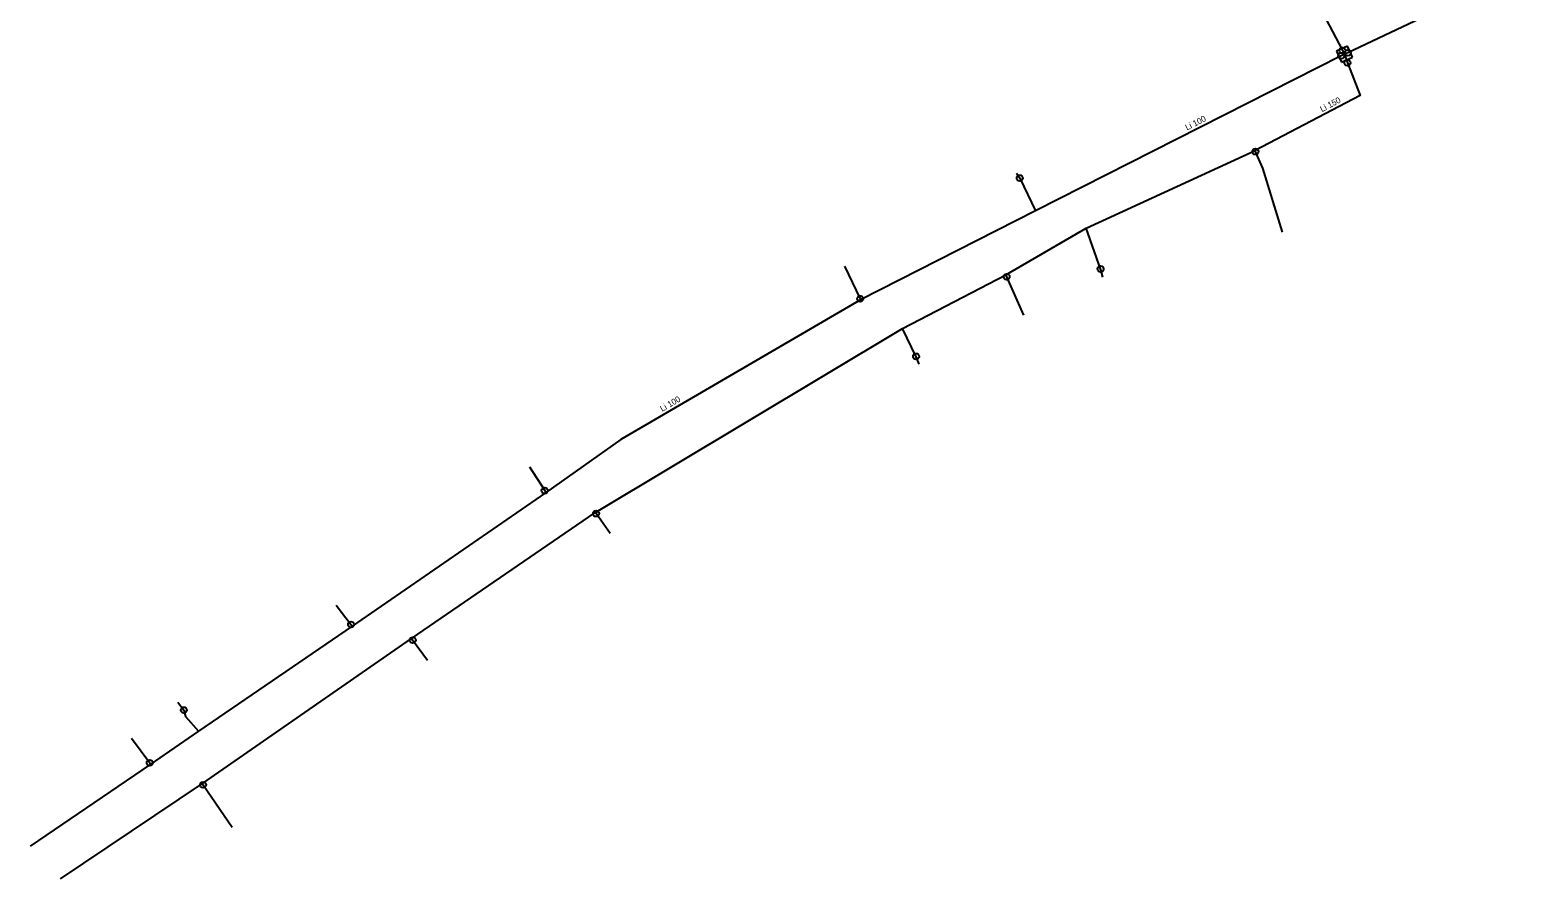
# Model space of a CAD drawing. Extents: x -684724 to -684366, y -1163865 to -1163489.
# Drawn here: x -684620.3 to -684495.3, y -1163846.5 to -1163776.1 of the extents above; entities that cross this region are included whole.
import ezdxf

# ---------------------------------------------------------------- set-up
doc = ezdxf.new("R2010")
doc.units = 0
for name, color, linetype in [('Popis vodovodních řadů', 7, 'Continuous'), ('Vod přípojky-voda pitná', 7, 'Continuous'), ('Vodovodní řad', 7, 'Continuous'), ('Vodovodní šachty', 7, 'Continuous'), ('Vodovodní šoupata', 7, 'Continuous')]:
    doc.layers.add(name, color=color, linetype=linetype)

msp = doc.modelspace()

# ---------------------------------------------------------------- linework, layer by layer
at = {"layer": 'Vod přípojky-voda pitná'}
for points in [[(-684516.44, -1163792.82), (-684518.07, -1163787.52), (-684518.61, -1163786.27), (-684518.69, -1163786.07)], [(-684538.49, -1163787.93), (-684538.23, -1163788.34), (-684536.91, -1163791.05)], [(-684531.33, -1163796.56), (-684531.5, -1163795.97), (-684532.73, -1163792.5)], [(-684552.77, -1163795.65), (-684551.46, -1163798.36), (-684551.44, -1163798.46)], [(-684539.38, -1163796.37), (-684539.32, -1163796.54), (-684537.92, -1163799.71)], [(-684546.57, -1163803.78), (-684546.82, -1163803.17), (-684547.94, -1163800.82)], [(-684578.89, -1163812.3), (-684577.63, -1163814.28), (-684577.56, -1163814.48)], [(-684572.21, -1163817.84), (-684573.37, -1163816.19), (-684573.46, -1163816.13)], [(-684594.92, -1163823.78), (-684593.69, -1163825.43), (-684593.6, -1163825.54)], [(-684587.34, -1163828.38), (-684588.58, -1163826.69), (-684588.68, -1163826.55)], [(-684608.06, -1163831.85), (-684607.56, -1163832.49), (-684607.42, -1163833.02), (-684606.34, -1163834.24)], [(-684611.9, -1163834.82), (-684610.39, -1163836.87), (-684610.35, -1163837)], [(-684603.56, -1163842.23), (-684605.95, -1163838.72), (-684606.02, -1163838.58)]]:
    msp.add_lwpolyline(points, dxfattribs=at)
at = {"layer": 'Vodovodní řad'}
for points in [[(-684473.97, -1163760.15), (-684474.96, -1163760.85), (-684476.34, -1163761.11), (-684481.86, -1163763.54), (-684494.87, -1163770.29), (-684511.01, -1163777.95)], [(-684518.01, -1163765.28), (-684511.46, -1163777.76)], [(-684511.46, -1163777.76), (-684511.3, -1163778.05)], [(-684511.56, -1163778.19), (-684536.91, -1163791.05), (-684551.44, -1163798.46), (-684571.3, -1163810.03), (-684577.56, -1163814.48), (-684593.6, -1163825.54), (-684606.34, -1163834.24), (-684610.35, -1163837), (-684620.31, -1163843.78)], [(-684511.56, -1163778.19), (-684536.91, -1163791.05)], [(-684511.05, -1163778.77), (-684509.99, -1163781.49), (-684518.69, -1163786.07)], [(-684511.3, -1163778.05), (-684511.56, -1163778.19)], [(-684511.01, -1163777.95), (-684511.3, -1163778.05)], [(-684511.3, -1163778.05), (-684511.05, -1163778.77)], [(-684617.78, -1163846.5), (-684606.02, -1163838.58), (-684588.68, -1163826.55), (-684573.46, -1163816.13), (-684547.94, -1163800.82), (-684539.38, -1163796.37), (-684532.73, -1163792.5), (-684518.69, -1163786.07)]]:
    msp.add_lwpolyline(points, dxfattribs=at)
at = {"layer": 'Vodovodní šachty'}
for p, q in [((-684511.05, -1163777.4), (-684511.96, -1163777.81)), ((-684511.96, -1163777.81), (-684511.55, -1163778.72)), ((-684510.64, -1163778.31), (-684511.05, -1163777.4)), ((-684511.55, -1163778.72), (-684510.64, -1163778.31))]:
    msp.add_line(p, q, dxfattribs=at)
at = {"layer": 'Vodovodní šoupata'}
for centre in [(-684511.46, -1163777.76), (-684511.01, -1163777.95), (-684511.56, -1163778.19), (-684511.05, -1163778.77), (-684518.68, -1163786.15), (-684538.23, -1163788.34), (-684539.32, -1163796.54), (-684531.52, -1163795.89), (-684551.46, -1163798.36), (-684546.83, -1163803.14), (-684577.63, -1163814.28), (-684573.37, -1163816.19), (-684593.69, -1163825.39), (-684588.58, -1163826.69), (-684607.56, -1163832.49), (-684610.39, -1163836.87), (-684605.96, -1163838.7)]:
    msp.add_circle(centre, 0.25, dxfattribs=at)

# ---------------------------------------------------------------- texts
at = {"layer": 'Popis vodovodních řadů'}
for s, rotation, p in [('Li 150', 27.764, (-684513.16, -1163782.88)), ('Li 100', 26.8986, (-684524.35, -1163784.4)), ('Li 100', 30.2241, (-684567.88, -1163807.75))]:
    msp.add_text(s, height=0.5, rotation=rotation, dxfattribs=at).set_placement(p)

doc.saveas('drawing.dxf')
